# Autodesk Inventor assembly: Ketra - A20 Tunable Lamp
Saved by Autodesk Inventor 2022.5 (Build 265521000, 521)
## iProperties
Created: 2024-07
Part Number: Ketra - A20 Tunable Lamp
Document SubType Name: Assembly
Designer: AdminForWorker
Title: Ketra - A20 Tunable Lamp v4
Author: AdminForWorker
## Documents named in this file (2)
- z:\worker\convert-fusion-r03-cosv3\tmp\job-1\56\temp\files\8d2a2a6e-beca-4914-beb0-95083099f5d5\Ketra - A20 Tunable Lamp v4.iam
- z:\worker\convert-fusion-r03-cosv3\tmp\job-1\56\temp\files\8d2a2a6e-beca-4914-beb0-95083099f5d5\Ketra A20.ipt
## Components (1 placed, 1 different names)
1. Ketra A20:1
